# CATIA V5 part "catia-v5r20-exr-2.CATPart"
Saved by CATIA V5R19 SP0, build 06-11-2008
Part number: Part1
Bounding box of the stored display mesh (mm): x 0 to 0, y -19.985 to 150, z 0 to 125
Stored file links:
  D:\Shriniwas\v5_r19\Part files\c02\exe2.CATPart
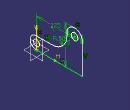
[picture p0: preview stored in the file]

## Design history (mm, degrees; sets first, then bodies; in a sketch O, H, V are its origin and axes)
Body1 (main body)
  Sketch1 on yz-plane, origin (0, 0, 0), H (0, 1, 0), V (0, 0, 1)
    line L1 (0, 0) -> (150, 0)
    line L2 (150, 0) -> (150, 100)
    arc A1 centre (125, 100) radius 25 from (150, 100) to (100, 100) ccw
    point P4 (125, 125)
    line L3 (100, 100) -> (100, 90)
    line L4 (0, 40) -> (50, 40)
    point P7 (0, 40)
    arc A2 centre (50, 90) radius 50 from (50, 40) to (100, 90) ccw
    arc A3 centre (0, 20) radius 20 from (0, 0) to (0, 40) cw
    circle A4 centre (125, 100) radius 11
    circle A5 centre (0, 20) radius 10
    distance P4 V = 125
    distance P4 H = 125
    radius A2 = 50
    radius A4 = 11
    horizontal: L1 H, L4 H
    vertical: L2 V
    coincidence: A1 P4, P7 V
    tangency: A1 L2, L3 A1, A3 L1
